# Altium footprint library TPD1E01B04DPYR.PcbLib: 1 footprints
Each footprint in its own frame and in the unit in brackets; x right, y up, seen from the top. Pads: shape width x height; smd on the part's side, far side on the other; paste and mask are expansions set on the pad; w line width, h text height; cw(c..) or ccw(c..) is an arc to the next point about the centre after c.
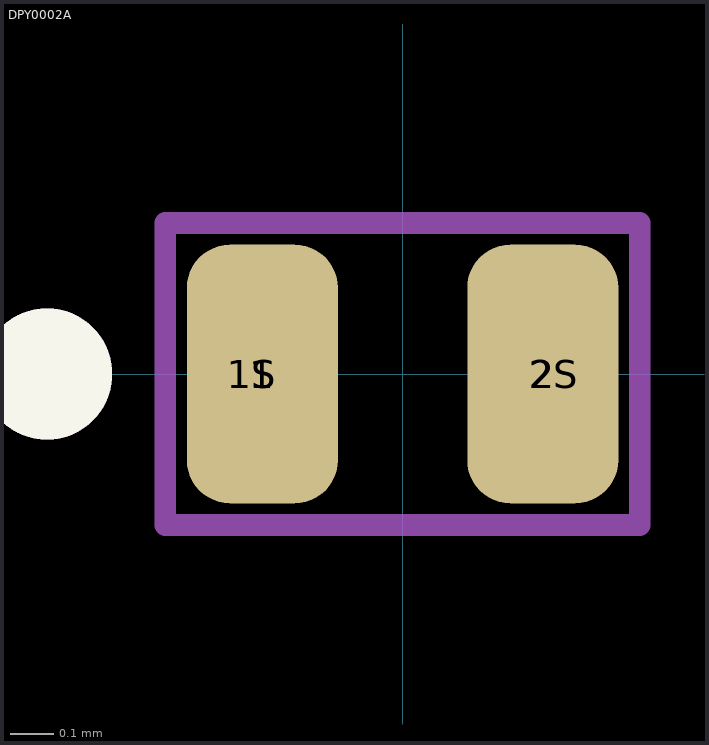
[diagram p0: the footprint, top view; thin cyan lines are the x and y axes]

## DPY0002A [mm] "X1SON-2"
height 0.45
pads (4):
  rrect57% 0.35x0.6 smd paste-0.5 mask-0.05: 1(-0.325,0) 2(0.325,0)
  rrect33% 0.3x0.5 on Top Paste: 1S(-0.35,0) 2S(0.35,0)
Top Overlay:
  circle w0.254: c-0.825,0 r0.025
M5 Assembly Top:
  circle w0.254: c-0.825,0 r0.025
  lines w0.05: -0.55,-0.35 -0.55,0.35 0.55,0.35 0.55,-0.35 -0.55,-0.35
  text ".Designator" at -0.475,-0.125 h0.25
3D body "DPY0002A.stp": height 0.45, standoff 0, extent -0.5,-0.3 0.5,0.3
